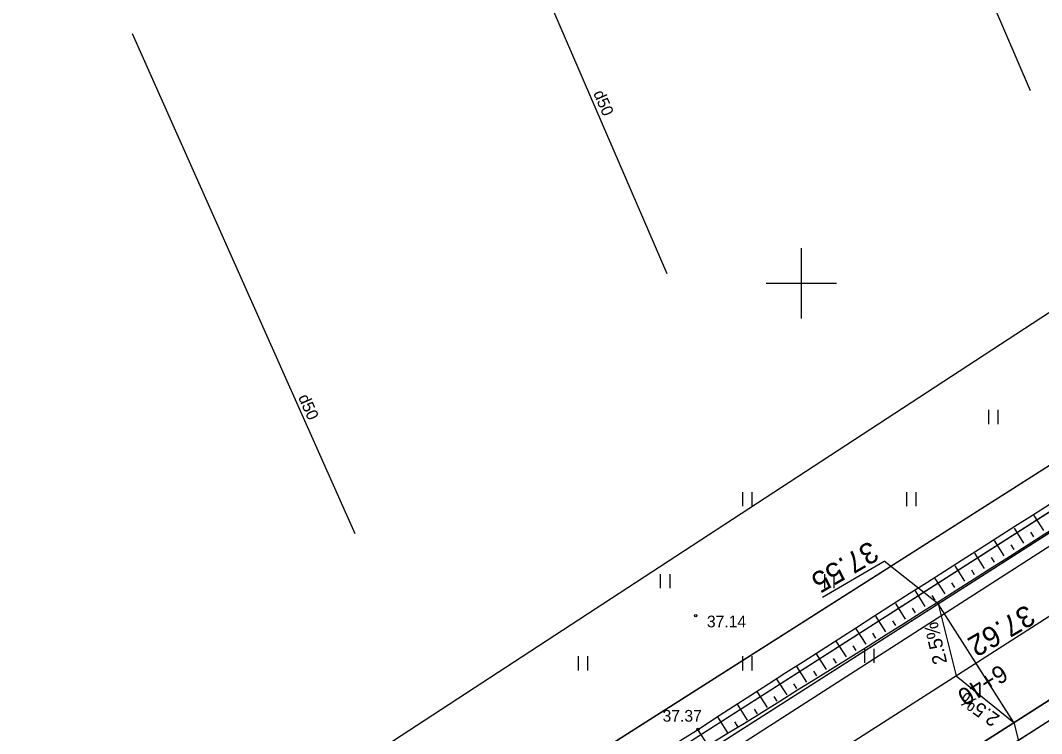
# Model space of a CAD drawing. Extents: x 469981 to 472086, y 246785 to 247785.
# Drawn here: x 471366.69 to 471410.25, y 247380.81 to 247411.21 of the extents above; entities that cross this region are included whole.
import ezdxf

# ---------------------------------------------------------------- set-up
doc = ezdxf.new("R2010")
doc.units = 0
for name, color, linetype in [('0_922', 7, 'Continuous'), ('0_Asfalta_mala', 7, 'Continuous'), ('0_Asfalta_Nomale', 7, 'Continuous'), ('0_Ruut_Braukt', 7, 'Continuous'), ('0_Ruut_nomale', 7, 'Continuous'), ('0_vertikals', 7, 'Continuous'), ('0_vertkals_cipari', 7, 'Continuous'), ('21', 7, 'Continuous'), ('6_piketaza', 7, 'Continuous'), ('CELI_CMAL_####_####_#', 7, 'Continuous'), ('DREN_VADP_####_####_#', 7, 'Continuous'), ('DREN_VADP_####_TKST_#', 7, 'Continuous'), ('GEOD_ELEM_####_####_#', 7, 'Continuous'), ('RAMI_UZMR_####_####_#', 7, 'Continuous'), ('RELJ_AATZ_####_TKST_#', 7, 'Continuous'), ('RELJ_ELEM_####_####_#', 7, 'Continuous'), ('RELJ_NOGA_####_####_#', 7, 'Continuous'), ('RELJ_NOGL_####_####_#', 7, 'Continuous'), ('ROBZ_IERR_####_####_#', 7, 'Continuous'), ('ROBZ_PROJ_####_####_#', 7, 'Continuous'), ('TERT_ELEM_####_####_#', 7, 'Continuous')]:
    doc.layers.add(name, color=color, linetype=linetype)

msp = doc.modelspace()

# ---------------------------------------------------------------- linework, layer by layer
at = {"layer": '0_922'}
msp.add_line((471711.11, 247577.663), (471337.911, 247339.41), dxfattribs=at)
at = {"layer": '0_Asfalta_mala'}
for p, q in [((471709.476, 247580.179), (471336.304, 247341.944)), ((471712.743, 247575.147), (471339.517, 247336.876))]:
    msp.add_line(p, q, dxfattribs=at)
at = {"layer": '0_Asfalta_Nomale'}
for p, q in [((471709.068, 247580.808), (471352.097, 247352.916)), ((471695.558, 247563.285), (471399.037, 247373.985))]:
    msp.add_line(p, q, dxfattribs=at)
at = {"layer": '0_Ruut_Braukt'}
for p, q in [((471709.476, 247580.179), (471336.304, 247341.944)), ((471339.517, 247336.876), (471712.743, 247575.147))]:
    msp.add_line(p, q, dxfattribs=at)
at = {"layer": '0_Ruut_nomale'}
for points in [[(471512.083, 247454.162), (471511.838, 247454.895), (471453.013, 247417.341), (471348.58, 247350.671), (471335.903, 247342.577), (471306.296, 247323.944), (471248.242, 247287.407), (471208.75, 247262.551), (471208.786, 247261.688), (471290.39, 247313.047), (471335.822, 247341.64), (471349.818, 247350.571), (471398.518, 247381.661), (471437.5, 247406.548), (471498.795, 247445.679), (471511.425, 247453.742)], [(471514.294, 247447.566), (471399.037, 247373.985), (471385.85, 247365.566), (471340.791, 247336.792), (471211.253, 247255.265), (471209.116, 247253.92), (471209.079, 247254.783), (471296.254, 247309.648), (471339.517, 247336.876), (471350.75, 247344.048), (471392.723, 247370.844), (471426.479, 247392.394), (471514.049, 247448.299)]]:
    msp.add_lwpolyline(points, close=True, dxfattribs=at)
at = {"layer": '0_vertikals'}
for p, q in [((471400.909, 247386.627), (471403.541, 247388.162)), ((471405.838, 247386.334), (471403.541, 247388.162)), ((471409.066, 247381.277), (471410.227, 247376.699))]:
    msp.add_line(p, q, dxfattribs=at)
msp.add_lwpolyline([(471405.838, 247386.334), (471406.609, 247383.268), (471409.066, 247381.277)], close=True, dxfattribs=at)
at = {"layer": '21'}
msp.add_line((471711.11, 247577.663), (471337.911, 247339.41), dxfattribs=at)
at = {"layer": '6_piketaza'}
msp.add_lwpolyline([(471407.586, 247383.595), (471407.317, 247384.016)], dxfattribs=at)
at = {"layer": 'CELI_CMAL_####_####_#'}
msp.add_lwpolyline([(471338.703, 247365.456), (471340.587, 247361.545), (471343.087, 247356.058), (471343.774, 247355.226), (471347.4, 247352.573), (471349.509, 247351.696), (471351.575, 247351.992), (471374.262, 247365.343), (471396.093, 247379.507), (471423.487, 247397.08), (471444.29, 247410.189)], dxfattribs=at)
at = {"layer": 'DREN_VADP_####_####_#'}
for points in [[(471400.778, 247429.101), (471409.76, 247408.224)], [(471394.283, 247400.398), (471385.918, 247419.754)], [(471371.448, 247410.651), (471380.95, 247389.33)]]:
    msp.add_lwpolyline(points, dxfattribs=at)
at = {"layer": 'GEOD_ELEM_####_####_#'}
for p, q in [((471400, 247401.5), (471400, 247400)), ((471398.5, 247400), (471400, 247400)), ((471400, 247400), (471400, 247398.5)), ((471400, 247400), (471401.5, 247400))]:
    msp.add_line(p, q, dxfattribs=at)
at = {"layer": 'RAMI_UZMR_####_####_#'}
msp.add_lwpolyline([(471355.9, 247363.1), (471457.4, 247429.3), (471524.252, 247472.902), (471743.701, 247613.609), (471760.558, 247620.637), (471763.718, 247625.03), (471767.054, 247626.612), (471778.292, 247625.909), (471806.563, 247631.532), (471842.307, 247641.196)], dxfattribs=at)
at = {"layer": 'RELJ_ELEM_####_####_#'}
for centre in [(471395.5, 247385.835), (471395.596, 247380.988)]:
    msp.add_circle(centre, 0.05, dxfattribs=at)
at = {"layer": 'RELJ_NOGA_####_####_#'}
for p, q in [((471410.343, 247389.467), (471409.935, 247390.104)), ((471409.501, 247388.927), (471409.091, 247389.568)), ((471408.66, 247388.388), (471408.247, 247389.032)), ((471409.922, 247389.197), (471409.799, 247389.389)), ((471409.081, 247388.657), (471408.957, 247388.85)), ((471407.818, 247387.848), (471407.403, 247388.495)), ((471408.239, 247388.118), (471408.114, 247388.311)), ((471406.976, 247387.308), (471406.559, 247387.959)), ((471407.397, 247387.578), (471407.272, 247387.773)), ((471406.134, 247386.769), (471405.715, 247387.423)), ((471405.292, 247386.229), (471404.871, 247386.887)), ((471406.555, 247387.039), (471406.429, 247387.234)), ((471405.713, 247386.499), (471405.587, 247386.696)), ((471404.45, 247385.69), (471404.027, 247386.35)), ((471404.871, 247385.96), (471404.744, 247386.157)), ((471403.608, 247385.151), (471403.183, 247385.814)), ((471404.029, 247385.42), (471403.902, 247385.619)), ((471402.765, 247384.612), (471402.339, 247385.278)), ((471401.923, 247384.072), (471401.495, 247384.741)), ((471403.187, 247384.881), (471403.059, 247385.081)), ((471402.344, 247384.342), (471402.216, 247384.542)), ((471401.081, 247383.533), (471400.652, 247384.205)), ((471401.502, 247383.803), (471401.373, 247384.004)), ((471400.238, 247382.995), (471399.808, 247383.668)), ((471400.66, 247383.264), (471400.531, 247383.466)), ((471399.396, 247382.456), (471398.964, 247383.131)), ((471398.553, 247381.917), (471398.121, 247382.595)), ((471399.817, 247382.725), (471399.688, 247382.928)), ((471397.711, 247381.379), (471397.277, 247382.058)), ((471398.975, 247382.186), (471398.845, 247382.389)), ((471398.132, 247381.648), (471398.002, 247381.851)), ((471396.868, 247380.84), (471396.433, 247381.521)), ((471397.289, 247381.11), (471397.159, 247381.313)), ((471396.025, 247380.302), (471395.59, 247380.984))]:
    msp.add_line(p, q, dxfattribs=at)
for points in [[(471341.934, 247360.736), (471344.51, 247356.259), (471349.946, 247353.745), (471355.895, 247354.991), (471376.693, 247368.011), (471396.058, 247380.323), (471444.047, 247411.052), (471471.484, 247428.432), (471497.591, 247445.096), (471529.061, 247465.658), (471552.024, 247480.39), (471579.849, 247498.336), (471608.29, 247516.955), (471640.013, 247537.434), (471663.526, 247552.835), (471700.309, 247577.155), (471731.58, 247596.998), (471755.893, 247610.638), (471758.96, 247612.207)], [(471398.635, 247372.113), (471402.433, 247374.78), (471425.587, 247389.134), (471450.058, 247404.807), (471474.143, 247419.972), (471503.215, 247438.678), (471533.565, 247458.24), (471556.869, 247473.387), (471582.759, 247490.013), (471614.043, 247510.505), (471643.167, 247529.241), (471669.12, 247546.6), (471690.757, 247560.622), (471694.708, 247563.158)]]:
    msp.add_spline(points, degree=3, dxfattribs=at)
at = {"layer": 'RELJ_NOGL_####_####_#'}
for points in [[(471342.514, 247361.025), (471345.404, 247356.891), (471350.224, 247354.862), (471355.251, 247356.423), (471376.007, 247368.362), (471395.596, 247380.988), (471443.663, 247411.567), (471471.284, 247429.247), (471497.369, 247445.866), (471528.273, 247466.831), (471551.61, 247481.241), (471579.417, 247499.099), (471607.686, 247517.412), (471639.588, 247538.317), (471662.844, 247553.564), (471699.582, 247577.982), (471731.348, 247598.063), (471755.711, 247611.433), (471758.267, 247612.728)], [(471399.82, 247371.525), (471403.248, 247373.923), (471426.144, 247388.265), (471450.973, 247403.909), (471474.455, 247419.142), (471503.701, 247437.899), (471533.875, 247457.475), (471557.479, 247472.578), (471583.176, 247489.002), (471614.915, 247509.524), (471643.61, 247528.29), (471669.945, 247545.695), (471691.536, 247559.696), (471695.147, 247562.053)]]:
    msp.add_spline(points, degree=3, dxfattribs=at)
at = {"layer": 'ROBZ_IERR_####_####_#'}
msp.add_lwpolyline([(471513.259, 247488.166), (471524.883, 247464.852), (471341.261, 247348.2), (471124.72, 247213.54), (471093.674, 247200.298), (471050.609, 247195.379), (471001.509, 247189.266), (470977.922, 247249.601)], dxfattribs=at)
at = {"layer": 'ROBZ_PROJ_####_####_#'}
msp.add_lwpolyline([(471341.261, 247348.2), (471524.883, 247464.852), (471765.831, 247617.357), (471863.461, 247637.05), (471867.531, 247625.725), (471827.071, 247615.935), (471808.63, 247612.294), (471769.199, 247605.751), (471757.886, 247600.963), (471700.012, 247564.123), (471398.351, 247372.094), (471346.741, 247338.478)], dxfattribs=at)
at = {"layer": 'TERT_ELEM_####_####_#'}
for p, q in [((471408, 247394), (471408, 247394.6)), ((471408.4, 247394), (471408.4, 247394.6)), ((471397.5, 247390.5), (471397.5, 247391.1)), ((471397.9, 247390.5), (471397.9, 247391.1)), ((471404.5, 247390.5), (471404.5, 247391.1)), ((471404.9, 247390.5), (471404.9, 247391.1)), ((471394, 247387), (471394, 247387.6)), ((471394.4, 247387), (471394.4, 247387.6)), ((471401, 247387), (471401, 247387.6)), ((471401.4, 247387), (471401.4, 247387.6)), ((471402.71, 247383.819), (471402.71, 247384.419)), ((471403.11, 247383.819), (471403.11, 247384.419)), ((471390.5, 247383.5), (471390.5, 247384.1)), ((471390.9, 247383.5), (471390.9, 247384.1)), ((471397.5, 247383.5), (471397.5, 247384.1)), ((471397.9, 247383.5), (471397.9, 247384.1))]:
    msp.add_line(p, q, dxfattribs=at)

# ---------------------------------------------------------------- texts
at = {"layer": '0_vertkals_cipari'}
for s, height, rotation, p in [('37.55', 0.9, 210.2507, (471402.943, 247389.048)), ('37.62', 0.9, 210.2507, (471409.622, 247386.335)), ('2.5%', 0.5993, 103.404, (471406.229, 247383.833)), ('2.5%', 0.5993, 144.6162, (471408.51, 247381.545))]:
    msp.add_text(s, height=height, rotation=rotation, dxfattribs=at).set_placement(p)
at = {"layer": '6_piketaza'}
msp.add_text('6+40', height=0.75, rotation=212.5544, dxfattribs=at).set_placement((471408.498, 247383.791))
at = {"layer": 'DREN_VADP_####_TKST_#'}
for rotation, p in [(293.3723, (471391.116, 247408.106)), (294.0217, (471378.525, 247395.141))]:
    msp.add_text('d50', height=0.5, rotation=rotation, dxfattribs=at).set_placement(p)
at = {"layer": 'RELJ_AATZ_####_TKST_#'}
for s, p in [('37.14', (471395.974, 247385.335)), ('37.37', (471394.083, 247381.314))]:
    msp.add_text(s, height=0.5, dxfattribs=at).set_placement(p)

doc.saveas('drawing.dxf')
